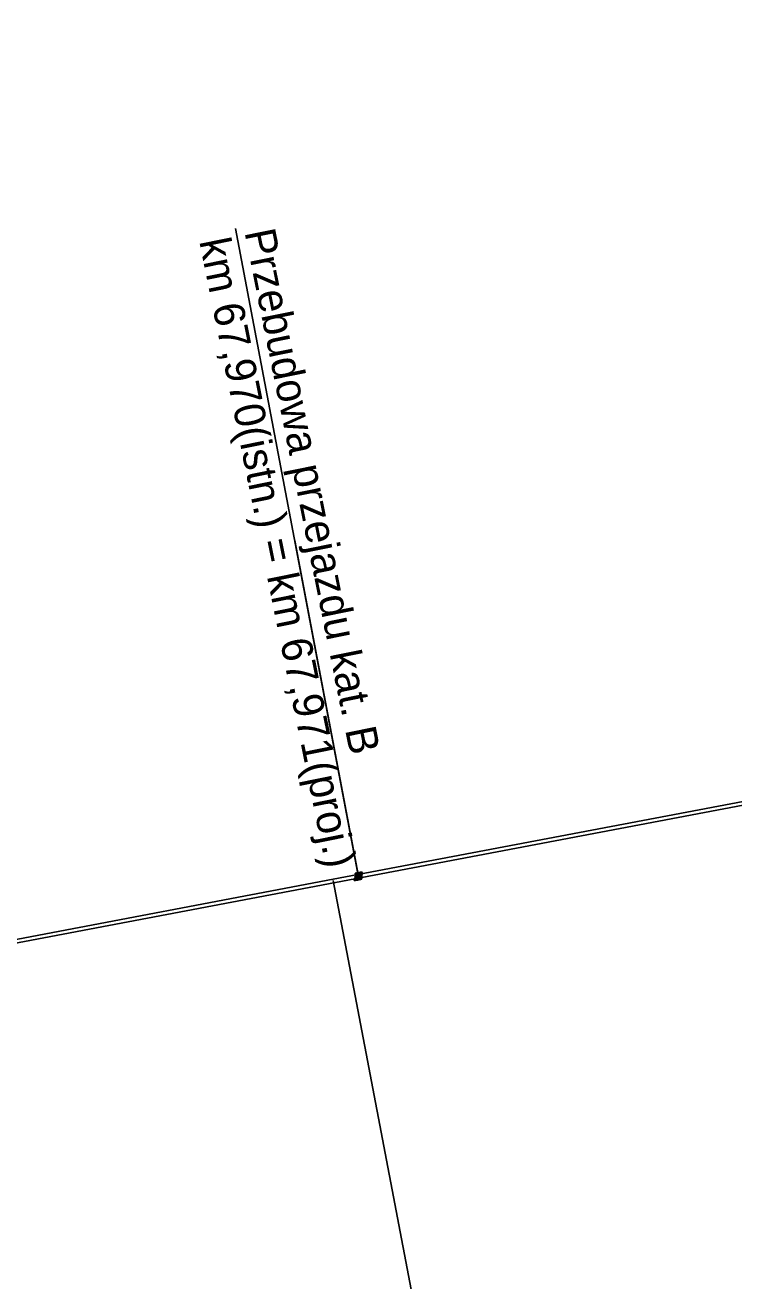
# Model space of a CAD drawing. Extents: x 6540402 to 6566579, y 5525343 to 5532423.
# Drawn here: x 6550860 to 6551666, y 5527039 to 5528468 of the extents above; entities that cross this region are included whole.
import ezdxf

# ---------------------------------------------------------------- set-up
doc = ezdxf.new("R2010")
doc.units = 0
for name, color, linetype in [('TOR_PS_OPIS_T-hektometry projektowane', 7, 'Continuous'), ('TOR_PS_OPIS_T-opisy dodatkowe', 7, 'Continuous'), ('TOR_PS_P-płyty przejazdowe', 7, 'Continuous'), ('TOR_PS_T-tory projektowane', 7, 'Continuous')]:
    doc.layers.add(name, color=color, linetype=linetype)

msp = doc.modelspace()

# ---------------------------------------------------------------- linework, layer by layer
at = {"layer": 'TOR_PS_OPIS_T-hektometry projektowane'}
msp.add_lwpolyline([(6551210.5, 5527494.8), (6551353.6, 5526743.3)], dxfattribs=at)
at = {"layer": 'TOR_PS_OPIS_T-opisy dodatkowe'}
for p, q in [((6551099.3, 5528236.6), (6551238.1, 5527504.6)), ((6551239.1, 5527499.5), (6551166.7, 5527881.5))]:
    msp.add_line(p, q, dxfattribs=at)
at = {"layer": 'TOR_PS_P-płyty przejazdowe'}
for points in [[(6551234.9, 5527495.9), (6551235.2, 5527494.7), (6551234.6, 5527494.6), (6551234.4, 5527495.8)], [(6551235.5, 5527496.2), (6551235.3, 5527497.5), (6551234.7, 5527497.4), (6551234.9, 5527496.1)], [(6551235.5, 5527496), (6551235.8, 5527494.9), (6551235.2, 5527494.7), (6551234.9, 5527495.9)], [(6551235.8, 5527497.7), (6551235.6, 5527498.9), (6551235, 5527498.8), (6551235.2, 5527497.6)], [(6551236.1, 5527496.3), (6551235.9, 5527497.6), (6551235.3, 5527497.5), (6551235.5, 5527496.2)], [(6551236.3, 5527501.9), (6551236, 5527503.1), (6551235.4, 5527503), (6551235.7, 5527501.8)], [(6551236, 5527500.2), (6551236.2, 5527499.1), (6551235.6, 5527499), (6551235.4, 5527500.1)], [(6551236.1, 5527496.2), (6551236.3, 5527495), (6551235.8, 5527494.9), (6551235.5, 5527496)], [(6551236.4, 5527497.8), (6551236.2, 5527499), (6551235.6, 5527498.9), (6551235.8, 5527497.7)], [(6551236.5, 5527500.5), (6551236.3, 5527501.8), (6551235.7, 5527501.7), (6551235.9, 5527500.4)], [(6551236.7, 5527496.4), (6551236.4, 5527497.7), (6551235.9, 5527497.6), (6551236.1, 5527496.3)], [(6551236.8, 5527502), (6551236.6, 5527503.2), (6551236, 5527503.1), (6551236.3, 5527501.9)], [(6551236.6, 5527500.4), (6551236.8, 5527499.2), (6551236.2, 5527499.1), (6551236, 5527500.2)], [(6551236.7, 5527496.3), (6551236.9, 5527495.1), (6551236.3, 5527495), (6551236.1, 5527496.2)], [(6551237, 5527497.9), (6551236.8, 5527499.1), (6551236.2, 5527499), (6551236.4, 5527497.8)], [(6551237.1, 5527500.6), (6551236.9, 5527501.9), (6551236.3, 5527501.8), (6551236.5, 5527500.5)], [(6551237.3, 5527496.5), (6551237, 5527497.8), (6551236.4, 5527497.7), (6551236.7, 5527496.4)], [(6551237.4, 5527502.2), (6551237.2, 5527503.3), (6551236.6, 5527503.2), (6551236.8, 5527502)], [(6551237.1, 5527500.5), (6551237.4, 5527499.3), (6551236.8, 5527499.2), (6551236.6, 5527500.4)], [(6551237.3, 5527496.4), (6551237.5, 5527495.2), (6551236.9, 5527495.1), (6551236.7, 5527496.3)], [(6551237.6, 5527498.1), (6551237.4, 5527499.2), (6551236.8, 5527499.1), (6551237, 5527497.9)], [(6551237.7, 5527500.7), (6551237.5, 5527502), (6551236.9, 5527501.9), (6551237.1, 5527500.6)], [(6551237.9, 5527496.6), (6551237.6, 5527497.9), (6551237, 5527497.8), (6551237.3, 5527496.5)], [(6551237.7, 5527500.6), (6551238, 5527499.4), (6551237.4, 5527499.3), (6551237.1, 5527500.5)], [(6551238, 5527502.3), (6551237.8, 5527503.4), (6551237.2, 5527503.3), (6551237.4, 5527502.2)], [(6551237.9, 5527496.5), (6551238.1, 5527495.3), (6551237.5, 5527495.2), (6551237.3, 5527496.4)], [(6551238.2, 5527498.2), (6551238, 5527499.3), (6551237.4, 5527499.2), (6551237.6, 5527498.1)], [(6551238.3, 5527500.8), (6551238.1, 5527502.1), (6551237.5, 5527502), (6551237.7, 5527500.7)], [(6551238.5, 5527496.7), (6551238.2, 5527498), (6551237.6, 5527497.9), (6551237.9, 5527496.6)], [(6551238.3, 5527500.7), (6551238.5, 5527499.5), (6551238, 5527499.4), (6551237.7, 5527500.6)], [(6551238.6, 5527502.4), (6551238.4, 5527503.6), (6551237.8, 5527503.4), (6551238, 5527502.3)], [(6551238.5, 5527496.6), (6551238.7, 5527495.4), (6551238.1, 5527495.3), (6551237.9, 5527496.5)], [(6551238.8, 5527498.3), (6551238.5, 5527499.5), (6551238, 5527499.3), (6551238.2, 5527498.2)], [(6551238.9, 5527501), (6551238.6, 5527502.2), (6551238.1, 5527502.1), (6551238.3, 5527500.8)], [(6551239, 5527496.9), (6551238.8, 5527498.1), (6551238.2, 5527498), (6551238.5, 5527496.7)], [(6551238.9, 5527500.8), (6551239.1, 5527499.6), (6551238.5, 5527499.5), (6551238.3, 5527500.7)], [(6551239.2, 5527502.5), (6551239, 5527503.7), (6551238.4, 5527503.6), (6551238.6, 5527502.4)], [(6551239.4, 5527498.4), (6551239.1, 5527499.6), (6551238.5, 5527499.5), (6551238.8, 5527498.3)], [(6551239.1, 5527496.7), (6551239.3, 5527495.5), (6551238.7, 5527495.4), (6551238.5, 5527496.6)], [(6551239.5, 5527501.1), (6551239.2, 5527502.3), (6551238.6, 5527502.2), (6551238.9, 5527501)], [(6551239.6, 5527497), (6551239.4, 5527498.2), (6551238.8, 5527498.1), (6551239, 5527496.9)], [(6551239.5, 5527500.9), (6551239.7, 5527499.7), (6551239.1, 5527499.6), (6551238.9, 5527500.8)], [(6551239.8, 5527502.6), (6551239.6, 5527503.8), (6551239, 5527503.7), (6551239.2, 5527502.5)], [(6551239.9, 5527498.5), (6551239.7, 5527499.7), (6551239.1, 5527499.6), (6551239.4, 5527498.4)], [(6551239.7, 5527496.8), (6551239.9, 5527495.6), (6551239.3, 5527495.5), (6551239.1, 5527496.7)], [(6551240.1, 5527501.2), (6551239.8, 5527502.5), (6551239.2, 5527502.3), (6551239.5, 5527501.1)], [(6551240.2, 5527497.1), (6551240, 5527498.4), (6551239.4, 5527498.2), (6551239.6, 5527497)], [(6551240.1, 5527501), (6551240.3, 5527499.8), (6551239.7, 5527499.7), (6551239.5, 5527500.9)], [(6551240.4, 5527502.7), (6551240.2, 5527503.9), (6551239.6, 5527503.8), (6551239.8, 5527502.6)], [(6551240.5, 5527498.6), (6551240.3, 5527499.8), (6551239.7, 5527499.7), (6551239.9, 5527498.5)], [(6551240.2, 5527496.9), (6551240.5, 5527495.8), (6551239.9, 5527495.6), (6551239.7, 5527496.8)], [(6551240.7, 5527501.3), (6551240.4, 5527502.6), (6551239.8, 5527502.5), (6551240.1, 5527501.2)], [(6551240.8, 5527497.2), (6551240.6, 5527498.5), (6551240, 5527498.4), (6551240.2, 5527497.1)], [(6551240.7, 5527501.1), (6551240.9, 5527500), (6551240.3, 5527499.8), (6551240.1, 5527501)], [(6551241, 5527502.8), (6551240.7, 5527504), (6551240.2, 5527503.9), (6551240.4, 5527502.7)], [(6551240.8, 5527497), (6551241.1, 5527495.9), (6551240.5, 5527495.8), (6551240.2, 5527496.9)], [(6551241.1, 5527498.7), (6551240.9, 5527499.9), (6551240.3, 5527499.8), (6551240.5, 5527498.6)], [(6551241.2, 5527501.4), (6551241, 5527502.7), (6551240.4, 5527502.6), (6551240.7, 5527501.3)], [(6551241.4, 5527497.3), (6551241.2, 5527498.6), (6551240.6, 5527498.5), (6551240.8, 5527497.2)], [(6551241.6, 5527502.9), (6551241.3, 5527504.1), (6551240.7, 5527504), (6551241, 5527502.8)], [(6551241.3, 5527501.3), (6551241.5, 5527500.1), (6551240.9, 5527500), (6551240.7, 5527501.1)], [(6551241.4, 5527497.2), (6551241.7, 5527496), (6551241.1, 5527495.9), (6551240.8, 5527497)], [(6551241.7, 5527498.8), (6551241.5, 5527500), (6551240.9, 5527499.9), (6551241.1, 5527498.7)], [(6551241.8, 5527501.5), (6551241.6, 5527502.8), (6551241, 5527502.7), (6551241.2, 5527501.4)], [(6551242, 5527497.4), (6551241.7, 5527498.7), (6551241.2, 5527498.6), (6551241.4, 5527497.3)], [(6551242.2, 5527503), (6551241.9, 5527504.2), (6551241.3, 5527504.1), (6551241.6, 5527502.9)], [(6551241.9, 5527501.4), (6551242.1, 5527500.2), (6551241.5, 5527500.1), (6551241.3, 5527501.3)], [(6551242, 5527497.3), (6551242.2, 5527496.1), (6551241.7, 5527496), (6551241.4, 5527497.2)], [(6551242.3, 5527499), (6551242.1, 5527500.1), (6551241.5, 5527500), (6551241.7, 5527498.8)], [(6551242.4, 5527501.6), (6551242.2, 5527502.9), (6551241.6, 5527502.8), (6551241.8, 5527501.5)], [(6551242.6, 5527497.5), (6551242.3, 5527498.8), (6551241.7, 5527498.7), (6551242, 5527497.4)], [(6551242.7, 5527503.2), (6551242.5, 5527504.3), (6551241.9, 5527504.2), (6551242.2, 5527503)], [(6551242.4, 5527501.5), (6551242.7, 5527500.3), (6551242.1, 5527500.2), (6551241.9, 5527501.4)], [(6551242.6, 5527497.4), (6551242.8, 5527496.2), (6551242.2, 5527496.1), (6551242, 5527497.3)], [(6551242.9, 5527499.1), (6551242.7, 5527500.2), (6551242.1, 5527500.1), (6551242.3, 5527499)], [(6551243, 5527501.7), (6551242.8, 5527503), (6551242.2, 5527502.9), (6551242.4, 5527501.6)], [(6551243, 5527501.6), (6551243.3, 5527500.4), (6551242.7, 5527500.3), (6551242.4, 5527501.5)], [(6551243.3, 5527503.3), (6551243.1, 5527504.4), (6551242.5, 5527504.3), (6551242.7, 5527503.2)], [(6551243.6, 5527501.8), (6551243.4, 5527503.1), (6551242.8, 5527503), (6551243, 5527501.7)]]:
    msp.add_lwpolyline(points, close=True, dxfattribs=at)
at = {"layer": 'TOR_PS_T-tory projektowane'}
for p, q in [((6556358, 5528467.8), (6550837.1, 5527421.3)), ((6553350.5, 5527901.9), (6551210.3, 5527496.2)), ((6551210.3, 5527496.2), (6550464, 5527354.7))]:
    msp.add_line(p, q, dxfattribs=at)

# ---------------------------------------------------------------- texts
at = {"layer": 'TOR_PS_OPIS_T-opisy dodatkowe'}
for s, p in [('km 67,970(istn.) = km 67,971(proj.)', (6551057.8, 5528222.2)), ('Przebudowa przejazdu kat. B', (6551109.3, 5528232.6))]:
    msp.add_text(s, height=35, rotation=281.4331, dxfattribs=at).set_placement(p)

doc.saveas('drawing.dxf')
